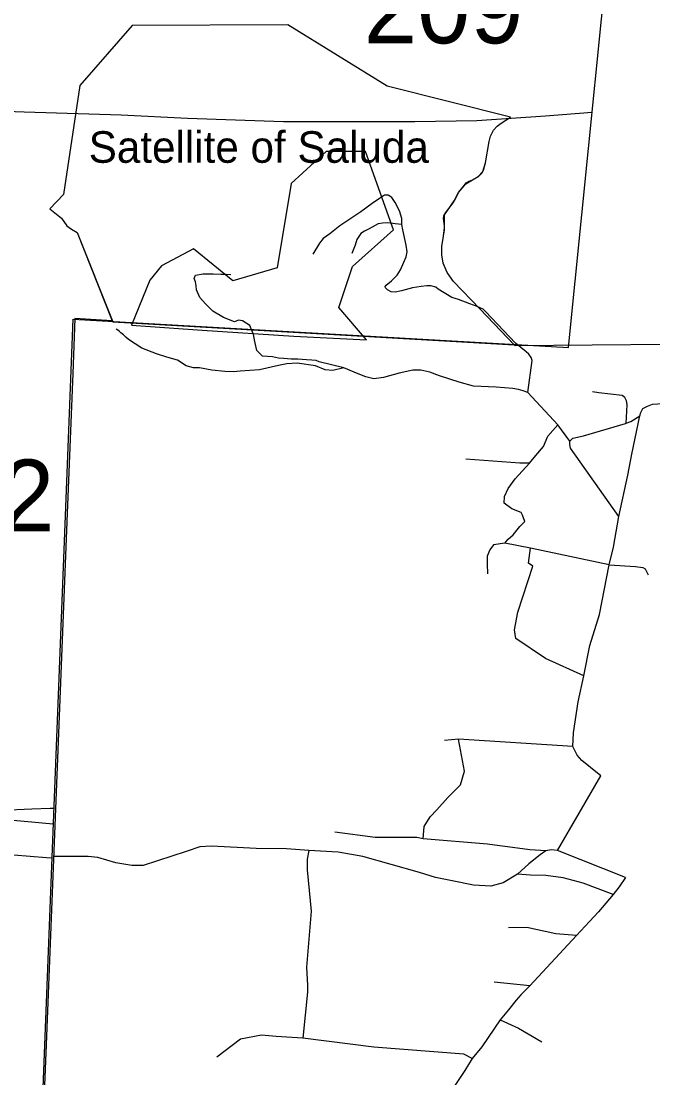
# Model space of a CAD drawing. Extents: x 884530 to 1028605, y 526725 to 653634.
# Drawn here: x 996952 to 1000565, y 556537 to 562581 of the extents above; entities that cross this region are included whole.
import ezdxf

# ---------------------------------------------------------------- set-up
doc = ezdxf.new("R2010")
doc.units = 0
for name, color, linetype in [('Exist Boundary Political City Limit New', 7, 'Continuous'), ('Exist Boundary Political City Limit New Hole', 7, 'Continuous'), ('Exist Boundary Political City Limit Old', 7, 'Continuous'), ('Exist Boundary Political CountyLine', 7, 'Continuous'), ('Exist Civil Demographics City Label', 7, 'Continuous'), ('Exist Hydrographic Creek Single Shore', 7, 'Continuous'), ('Exist Railroad Mainline', 7, 'Continuous'), ('Exist Road Non-System Type 51', 7, 'Continuous'), ('Exist Road Primary US Attributed', 7, 'Continuous'), ('Exist Road Secondary Structure Standard Bridge Number Label', 7, 'Continuous'), ('Exist Utilities Electrical Transmission Line', 7, 'Continuous'), ('Map Preparation Boundary City Limit Buffer Line', 7, 'Continuous')]:
    doc.layers.add(name, color=color, linetype=linetype)

msp = doc.modelspace()

# ---------------------------------------------------------------- linework, layer by layer
at = {"layer": 'Exist Boundary Political City Limit New'}
for points in [[(999627.9, 561891.8), (999636.9, 561923.4), (999653.9, 561956.9), (999674.8, 561980.3), (999697.4, 561997.4), (999750.2, 562031.6), (999045.8, 562208.9), (998477.8, 562559.3), (997586.9, 562555.4), (997287.3, 562212.8), (997193.9, 561589.8), (997116.1, 561508), (997182.2, 561453.4), (997213.4, 561410.6), (997240.6, 561391.1), (997271.8, 561371.7), (997473.4, 560867.4), (997258.8, 560880.4), (997248.1, 560565.8), (997215.4, 559766.4), (997165.4, 558509.2), (997096.1, 556728.4), (997064.9, 555976.8)], [(1000657, 560730.8), (999777.2, 560723.6), (999575.9, 560934.8), (999425.1, 561092.1), (999388.7, 561143.2), (999366.4, 561196.1), (999358.1, 561244.2), (999357.7, 561292.2), (999367.6, 561350.1), (999373.2, 561398.8), (999374.1, 561472.9), (999429.3, 561553.1), (999453.9, 561601.2), (999495.6, 561650.9), (999532.4, 561672.6), (999565.8, 561691.6), (999592.1, 561720.8), (999607.8, 561770.4), (999627.9, 561891.8)]]:
    msp.add_lwpolyline(points, dxfattribs=at)
at = {"layer": 'Exist Boundary Political City Limit New Hole'}
for points in [[(998927.5, 560758.8), (998769.6, 560943.4), (998847.4, 561177), (999080.8, 561387.3), (998921.3, 561835.1), (998695.6, 561835.1), (998497.2, 561652), (998415.5, 561169.2), (998162.6, 561095.2), (997937, 561278.2), (997754.1, 561180.9), (997688, 561099.1), (997583.5, 560842.6)], [(998497.2, 561652.1), (998415.5, 561169.2), (998162.6, 561095.2), (997937, 561278.2), (997754.1, 561180.9), (997688, 561099.1), (997583.5, 560842.6), (997986.9, 560813.2), (998510.7, 560779.1), (998927.6, 560758.8), (998769.6, 560943.4), (998847.4, 561177), (999080.8, 561387.2), (998921.3, 561835.1), (998695.6, 561835.1), (998497.2, 561652.1)], [(997583.5, 560842.6), (997986.9, 560813.3), (998510.7, 560779), (998927.5, 560758.8)]]:
    msp.add_lwpolyline(points, dxfattribs=at)
at = {"layer": 'Exist Boundary Political City Limit Old'}
for points in [[(999750.2, 562031.6), (999045.8, 562208.9), (998477.8, 562559.3), (997586.9, 562555.4), (997287.3, 562212.8), (997193.9, 561589.7), (997116.1, 561508), (997182.2, 561453.5), (997213.4, 561410.6), (997240.6, 561391.2), (997271.7, 561371.7), (997476.1, 560860.8)], [(999575.9, 560934.7), (999425.1, 561092), (999388.7, 561143.2), (999366.3, 561196.1), (999358.1, 561244.2), (999357.7, 561292.3), (999367.7, 561350.1), (999372.8, 561387.8), (999373.7, 561409.8), (999366.9, 561452.1), (999369.4, 561468.1), (999380, 561485.7), (999421.9, 561542.4), (999436.8, 561563.8), (999453.9, 561601.2), (999487.4, 561642.2), (999497.9, 561655.9), (999510, 561663.5), (999532.4, 561672.7), (999554.8, 561684), (999567, 561691.6), (999575.4, 561699.4), (999587.8, 561713), (999596.3, 561728.6), (999607.8, 561770.4), (999627.8, 561891.8), (999636.9, 561923.4), (999654, 561956.9), (999674.8, 561980.3), (999697.4, 561997.4), (999750.2, 562031.6)], [(999770.7, 560730.4), (999575.9, 560934.7)], [(997476.1, 560860.8), (999770.7, 560730.4)]]:
    msp.add_lwpolyline(points, dxfattribs=at)
at = {"layer": 'Exist Boundary Political CountyLine'}
msp.add_lwpolyline([(999167.8, 551397.9), (999229.7, 552060.2), (999297, 552754.5), (999373.1, 553532.6), (999431, 554135), (999500.6, 554839.1), (999504.7, 554901), (997102.8, 554995.1), (997020.3, 554998), (997026.3, 555160.3), (997250.5, 560876.2), (1000082.8, 560713.6), (1000385.5, 563731), (1000441.4, 564287.1), (1000460.4, 564476.5), (1000472.3, 564594.7), (1000608.5, 565973.2), (1000710.3, 567046.5), (1001034.2, 570277.9), (1001120.4, 571179.7), (1001306.5, 573042.7)], dxfattribs=at)
at = {"layer": 'Exist Hydrographic Creek Single Shore'}
msp.add_lwpolyline([(997136.1, 557987.9), (995932.3, 558099.1), (995818, 558095), (995775.1, 558095), (995764, 558103.3), (995752.9, 558139.3), (995742.9, 558162.1), (995657.4, 558216.9), (995545.2, 558247.3), (995489.8, 558254.3), (995459.4, 558300), (995186.5, 558481.8), (995086.2, 558586.6)], dxfattribs=at)
at = {"layer": 'Exist Railroad Mainline'}
msp.add_lwpolyline([(995595.1, 557963.6), (995653.6, 557960.2), (995779.7, 557962.7), (995818.3, 557967), (995877.7, 557974.3), (996042.9, 558001.3), (996158.9, 558019.8), (996331.8, 558039.1), (996504.3, 558049.8), (996696.1, 558060.5), (996839.6, 558068.3), (997012.5, 558076.6), (997118.3, 558079.1), (997140.8, 558079)], dxfattribs=at)
at = {"layer": 'Exist Road Non-System Type 51'}
for p, q in [((1000022, 560272.6), (999849.8, 560456)), ((1000090.7, 560179.3), (1000022, 560272.6)), ((999864.6, 559566.7), (999717.9, 559595.5)), ((1000315.4, 559470.5), (999864.6, 559566.7)), ((999453.7, 558473.5), (999372.4, 558466.7)), ((1000107.2, 558432.9), (999453.7, 558473.5)), ((1000018.6, 557838.5), (1000266.7, 558264.5)), ((1000408.4, 557683.1), (1000018.6, 557838.5)), ((999860.5, 557063), (999658, 557083.9))]:
    msp.add_line(p, q, dxfattribs=at)
for points in [[(999129.6, 561417.1), (999128.3, 561451.9), (999115.7, 561496.6), (999092, 561542.8), (999072.3, 561572.2), (999051.3, 561586.2), (999030.4, 561586.2), (999002.3, 561566.8), (998959.1, 561536.9), (998895.6, 561491), (998774.9, 561409.9), (998717.7, 561365.2), (998679.2, 561338.1), (998658.4, 561311.1), (998620.9, 561247.5)], [(999129.6, 561417.1), (999091.4, 561421.1), (999049.7, 561426.8), (999019, 561425.4), (998993.2, 561421.3), (998942.4, 561393.7), (998914.9, 561378.9), (998894.9, 561366), (998883.5, 561348.7), (998872.8, 561331.5), (998862, 561298.6), (998842.9, 561251.9)], [(999594.8, 560932.9), (999559.4, 560948.1), (999518.8, 560964.8), (999453.3, 560987.8), (999416, 561001.1), (999337.9, 561047), (999324.3, 561058.6), (999295.6, 561067.3), (999271.6, 561066.5), (999239.1, 561063.9), (999191, 561056.1), (999127.2, 561039.2), (999090.8, 561031.4), (999068.4, 561033), (999047.8, 561043.1), (999035.1, 561055), (999034.6, 561062.8), (999038.9, 561071), (999071, 561096.4), (999103.2, 561128.6), (999121.3, 561158), (999141, 561201.4), (999154.8, 561232.1), (999159.1, 561261.5), (999153.5, 561299.3), (999135.1, 561386.6), (999129.6, 561417.1)], [(998797.1, 560597.1), (998656.2, 560632.9), (998638.9, 560640.5), (998614, 560642.7), (998583.7, 560643.8), (998534.9, 560648.1), (998495.8, 560648.1), (998454.7, 560651.3), (998424.3, 560653.5), (998389.7, 560660), (998333.3, 560664.3), (998300.8, 560696.9), (998287.8, 560748.9), (998280.2, 560789), (998260.6, 560840), (998218.4, 560867), (998195.6, 560871.4), (998172.8, 560861.6), (998109, 560886.5), (998049, 560922.8), (998006.8, 560963.7), (997974.5, 561000.3), (997955.9, 561043.1), (997952.5, 561066), (997948.9, 561088.9), (997941.5, 561108.6), (997949.6, 561128.3), (997993.8, 561134.8), (998051, 561134.6), (998093.4, 561133.7), (998124.8, 561132.9), (998150.9, 561132.2)], [(999849.8, 560456), (999875.3, 560639.5), (999869.2, 560657.8), (999854.5, 560676.7), (999841, 560688.6), (999778.4, 560739.3), (999606.9, 560920.2), (999594.8, 560932.9)], [(998797.1, 560597.1), (998734.3, 560583.1), (998690.9, 560587.4), (998635.6, 560609.1), (998530.5, 560625.3), (998472, 560620.4), (998423.2, 560611.3), (998314.8, 560587.4), (998204.3, 560579.8), (998166.4, 560574.4), (998116.5, 560576.6), (998042.8, 560585.2), (997971.3, 560597.1), (997938.8, 560598.2), (997895.4, 560610.1), (997846.6, 560642.7), (997785.9, 560658.9), (997725.9, 560677.6), (997643, 560710.2), (997566.7, 560759.4), (997551.7, 560772.6), (997537.5, 560785.8), (997523.1, 560798.6), (997514.4, 560805.6), (997505.4, 560812.5), (997496.4, 560819.3)], [(999849.8, 560456), (999823.1, 560467), (999796.3, 560474.2), (999764.8, 560479.1), (999668.8, 560487.6), (999539.4, 560493.1), (999457.2, 560515.2), (999345.5, 560551.6), (999289.2, 560573.2), (999237.2, 560584.2), (999191.6, 560584.2), (999113.2, 560568.3), (999024.7, 560541.9), (998969.5, 560534.3), (998922.9, 560546.2), (998879.5, 560563.5), (998797.1, 560597.1)], [(1000489.7, 560323.1), (1000496.5, 560342.2), (1000506.6, 560364.7), (1000533.6, 560379.3), (1000561.7, 560390.6), (1000801.1, 560406.3), (1000832.7, 560417.5), (1000857.3, 560449), (1000869.1, 560477.3), (1000874.2, 560501.9), (1000881.1, 560549.7)], [(1000412.4, 560280.8), (1000416.5, 560350.5), (1000418.7, 560388.1), (1000414.4, 560409.5), (1000404.7, 560427.7), (1000389.8, 560440.6), (1000255.6, 560455.7), (1000220.3, 560459.9)], [(1000090.7, 560179.3), (1000106.5, 560195), (1000167.2, 560208.4), (1000408.8, 560279.3), (1000412.4, 560280.8)], [(1000369.5, 559747.4), (1000421.2, 559983.6), (1000443.7, 560103.9), (1000489.7, 560323.1)], [(1000412.4, 560280.8), (1000439.2, 560291.6), (1000489.7, 560323.1)], [(999860, 560053), (999896.3, 560096.8), (999940.2, 560148.8), (999964.2, 560206.7), (1000022, 560272.6)], [(1000369.5, 559747.4), (1000094.1, 560138.7), (1000089.6, 560160.1), (1000090.7, 560179.3)], [(999860, 560053), (999831, 560053), (999804, 560053), (999495.8, 560075.6)], [(999717.9, 559595.5), (999736.5, 559618.4), (999766.6, 559643.6), (999803.2, 559691.5), (999833.1, 559719.7), (999819.4, 559755.2), (999812.1, 559770.2), (999757.6, 559790.7), (999715.3, 559824.9), (999717, 559862.7), (999736.8, 559907.1), (999777.8, 559963.6), (999860, 560053)], [(1000315.4, 559470.5), (1000339.8, 559573.3), (1000369.5, 559747.4)], [(999717.9, 559595.5), (999652.9, 559585.2), (999632.3, 559557.9), (999616.9, 559520.2), (999616.9, 559477.4), (999618.7, 559419.2)], [(1000169.8, 558837), (999951.7, 558935.8), (999780.2, 559050.1), (999773.5, 559100.2), (999793.3, 559200), (999877.5, 559463.8), (999853, 559481.4), (999864.6, 559566.7)], [(1000169.8, 558837), (1000204.1, 559009.9), (1000258.9, 559188), (1000315.4, 559470.5)], [(1000315.4, 559470.5), (1000466, 559462), (1000507.1, 559456.8), (1000520.9, 559448.3), (1000538, 559413.9)], [(1000107.2, 558432.9), (1000111.6, 558510), (1000137, 558687.1), (1000169.8, 558837)], [(999250.5, 557904.6), (999257.2, 557975.7), (999291.1, 558029.9), (999328.4, 558070.5), (999392.8, 558141.6), (999463.8, 558212.8), (999487.5, 558290.6), (999453.7, 558473.5)], [(1000266.7, 558264.5), (1000207.2, 558312.7), (1000158.9, 558351.4), (1000132.6, 558382.9), (1000107.2, 558432.9)], [(999250.5, 557904.6), (999215.7, 557911.8), (998976.2, 557911.3), (998746, 557941.8)], [(998598.2, 557838.5), (998469.2, 557846.8), (998295.9, 557849.6), (998040.7, 557862.1), (997974, 557857.9), (997896.4, 557831.6), (997649.5, 557752.6), (997584.3, 557751.2), (997494.1, 557767.8), (997391.5, 557798.3), (997336, 557803.9), (997140.4, 557803.9)], [(999953.4, 557835.7), (999861.8, 557841.3), (999619.6, 557874.1), (999250.5, 557904.6)], [(998598.2, 557838.5), (998588.6, 557787.2), (998588.6, 557727.6), (998610.7, 557490.4), (998584.4, 557171.3), (998589.9, 557065.9), (998589.9, 557028.4), (998563.6, 556763.5)], [(999789.8, 557702.6), (999709.3, 557652.6), (999638.5, 557634.6), (999538.7, 557640.1), (999416.6, 557665.1), (999320.9, 557683.1), (999229.4, 557710.9), (998906.2, 557803.8), (998764.7, 557827.4), (998598.2, 557838.5)], [(1000018.6, 557838.5), (999982.5, 557841.3), (999953.4, 557835.7), (999920.1, 557813.5), (999856.3, 557762.2), (999789.8, 557702.6)], [(1000337.7, 557586), (1000165.6, 557651.2), (1000051.9, 557681.7), (999952.1, 557694.2), (999864.7, 557697), (999789.8, 557702.6)], [(1000408.4, 557683.1), (1000372.3, 557629), (1000337.7, 557586)], [(1000337.7, 557586), (1000254.4, 557486.1), (1000201.7, 557432), (1000128.2, 557351.6)], [(1000128.2, 557351.6), (1000010.3, 557361.3), (999843.9, 557397.4), (999739.8, 557396)], [(1000128.2, 557351.6), (999860.5, 557063), (999810.6, 557011.7), (999782.8, 556982.6), (999739.8, 556925.8), (999691.2, 556868.9)], [(999691.2, 556868.9), (999585.8, 556714.9), (999531.7, 556648.3)], [(999691.2, 556868.9), (999795.9, 556821.4), (999929.9, 556742.5)], [(998563.6, 556763.5), (998411, 556773.2), (998326.4, 556781.5), (998207.1, 556759.3), (998070.6, 556656.1)], [(999531.7, 556648.3), (999483.2, 556672), (998968.6, 556713.6), (998563.6, 556763.5)], [(999531.7, 556648.3), (999488.8, 556580.4), (999377.8, 556409.8)]]:
    msp.add_lwpolyline(points, dxfattribs=at)
at = {"layer": 'Exist Road Primary US Attributed'}
msp.add_lwpolyline([(995617.9, 557897), (995834.6, 557881.7), (995995.2, 557870.6), (996241.7, 557855.4), (996474.9, 557833.7), (996698, 557819), (996797.9, 557811.6), (996910.1, 557812.1), (997098, 557796.7), (997125.8, 557796.4), (997129.7, 557796.2)], dxfattribs=at)
at = {"layer": 'Exist Utilities Electrical Transmission Line'}
msp.add_lwpolyline([(994918.9, 562733.3), (995296.1, 562522.6), (995596.6, 562352.5), (996004.9, 562112.8), (996042.5, 562101.4), (996066.4, 562098.5), (996190.2, 562088.4), (996495.9, 562078.3), (996969.7, 562062.5), (997523.5, 562043.9), (997903.1, 562025.2), (998452.8, 562006.9), (999203.2, 562006), (999557.7, 562012.1), (999950.9, 562038.9), (1000217.8, 562059.7)], dxfattribs=at)
at = {"layer": 'Map Preparation Boundary City Limit Buffer Line'}
for points in [[(999627.9, 561891.8), (999636.9, 561923.4), (999653.9, 561956.9), (999674.8, 561980.3), (999697.4, 561997.4), (999750.2, 562031.6), (999045.8, 562208.9), (998477.8, 562559.3), (997586.9, 562555.4), (997287.3, 562212.8), (997193.9, 561589.8), (997116.1, 561508), (997182.2, 561453.4), (997213.4, 561410.6), (997240.6, 561391.1), (997271.8, 561371.7), (997473.4, 560867.4), (997258.8, 560880.4), (997248.1, 560565.8), (997215.4, 559766.4), (997165.4, 558509.2), (997096.1, 556728.4), (997064.9, 555976.8)], [(1000657, 560730.8), (999777.2, 560723.6), (999575.9, 560934.8), (999425.1, 561092.1), (999388.7, 561143.2), (999366.4, 561196.1), (999358.1, 561244.2), (999357.7, 561292.2), (999367.6, 561350.1), (999373.2, 561398.8), (999374.1, 561472.9), (999429.3, 561553.1), (999453.9, 561601.2), (999495.6, 561650.9), (999532.4, 561672.6), (999565.8, 561691.6), (999592.1, 561720.8), (999607.8, 561770.4), (999627.9, 561891.8)], [(998497.2, 561652.1), (998415.5, 561169.2), (998162.6, 561095.2), (997937, 561278.2), (997754.1, 561180.9), (997688, 561099.1), (997583.5, 560842.6), (997986.9, 560813.2), (998510.7, 560779.1), (998927.6, 560758.8), (998769.6, 560943.4), (998847.4, 561177), (999080.8, 561387.2), (998921.3, 561835.1), (998695.6, 561835.1), (998497.2, 561652.1)]]:
    msp.add_lwpolyline(points, dxfattribs=at)

# ---------------------------------------------------------------- texts
at = {"layer": 'Exist Civil Demographics City Label'}
msp.add_text('Satellite of Saluda', height=180.446, dxfattribs=at).set_placement((997338.6, 561770.6))
at = {"layer": 'Exist Road Secondary Structure Standard Bridge Number Label'}
for s, p in [('209', (998911.2, 562453.8)), ('342', (996227.2, 559663))]:
    msp.add_text(s, height=410.1, dxfattribs=at).set_placement(p)

doc.saveas('drawing.dxf')
